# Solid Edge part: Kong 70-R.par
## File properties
Title: Kong 70/R 70x39 Cm
Author: DESYS
Template: Normal.par
Last saved by: s.pallini
Revision: 15
Application: Solid Edge
Tipo di contenuto documento: 0
Precisione: 0,990
Document Number: 8052/R
Revision: 0
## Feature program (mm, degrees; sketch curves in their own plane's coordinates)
thicken "Assegnare_spessore_2"  Distance1 = 10 mm
thicken "Assegnare_spessore_1"  Distance1 = 10 mm
fillet "Rotondo_1" radius 30
fillet "Rotondo_2" radius 5
fillet "Rotondo_3" radius 5
sketch for "unnamed Cutout 1" plane through (0, 0, 0) normal (0, 0, 1) x-axis (1, 0, 0)
  circle centre (0, 0) radius 25
extrude "unnamed Cutout 1" cut through
sketch for "ExtrudedProtrusion_1" plane through (0, 0, 25) normal (0, 0, 1) x-axis (1, 0, 0)
extrude "ExtrudedProtrusion_1" add  Profile_Plane1_Distance = 25 mm
fillet "Rotondo_4" radius 10
sketch for "ExtrudedCutout_2" #1 plane through (0.4335, 0, 25) normal (0, 0, -1) x-axis (0, -1, 0)
sketch for "ExtrudedCutout_2" #2 plane through (0.4335, 0, 25) normal (0, 0, -1) x-axis (0, -1, 0)
extrude "ExtrudedCutout_2" cut finite 25 along -normal
fillet "Rotondo_5" radius 5
sketch for "unnamed Cutout 2" plane through (0, 0, 25) normal (0, 0, -1) x-axis (0, 1, 0)
  arc centre (0, 0) radius 25 from (-2.1303, -24.9091) to (24.1476, 6.4726) cw
  arc centre (0, 0) radius 25 from (24.1476, 6.4726) to (-2.1303, -24.9091) cw
extrude "unnamed Cutout 2" cut through along -normal
sketch for "ExtrudedProtrusion_2" plane through (-0.2145, -0.0446, 124) normal (0, 0, -1) x-axis (-1, 0, 0)
extrude "ExtrudedProtrusion_2" add finite 69.2647 along +normal  Profile_Plane1_Distance = 99 mm
sketch for "Foro_1" plane through (0, 0, 0) normal (0, 0, 1) x-axis (1, 0, 0)
  hole centre (118, 0) bore radius 17.5
  dimension (linear) = 118
hole "Foro_1" diameter 35 through
sketch for "ExtrudedCutout_4" plane through (0, 0, 0) normal (0, 0, 1) x-axis (1, 0, 0)
extrude "ExtrudedCutout_4" cut finite 120 along +normal
fillet "Rotondo_6" radius 3
fillet "Rotondo_7" radius 5
fillet "Rotondo_8" radius 8
Other named dimensions: "CurveByTable_2": Tolerance = 1 mm | "CurveByTable_3": Tolerance = 1 mm | "CurveByTable_4": Tolerance = 1 mm
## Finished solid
Body 1: solid body, 62 faces, 130 edges, 70 vertices.
  Faces by surface: blend 38, cylinder 9, plane 7, torus 4, swept 2, offset 1, spline 1
  Edges by curve: intersection 70, circle 49, line 10, ellipse 1
Body 2: sheet body, 1 face, 4 edges, 4 vertices.
  Faces by surface: spline 1
  Edges by curve: spline 4
Bounding box of the edges (mm; curved faces can reach further): 374.063 x 730.000 x 122.976, from (-190.6216, -370, 25) to (183.4413, 360, 147.9764).
Cylindrical faces by radius (mm): R5 x2, R8 x2, R17.5 x1, R25 x1, R35 x1, R37.5 x1, R112 x1
Toroidal faces (ring radius, tube radius in mm): R20.5 r3 x1, R30 r5 x1, R45.5 r8 x1, R107 r5 x1
Planar faces by outward normal: +z 1, -z 4, oblique 2
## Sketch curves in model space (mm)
arc centre (-31.4438, 0, 329.9271) radius 287.5849 from (-190, 0, 90) through (3.2769, 0, 44.4458) to (180, 0, 135)
circle centre (0, 0, 20) radius 25
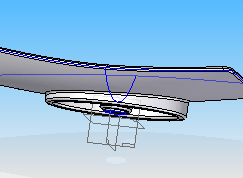
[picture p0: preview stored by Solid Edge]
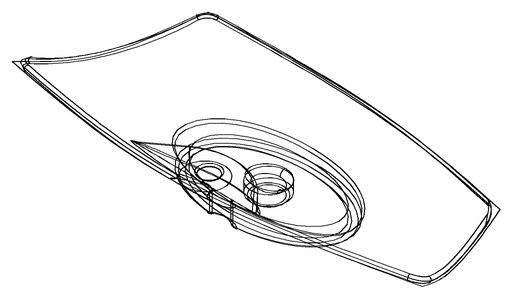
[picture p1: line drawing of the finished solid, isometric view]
